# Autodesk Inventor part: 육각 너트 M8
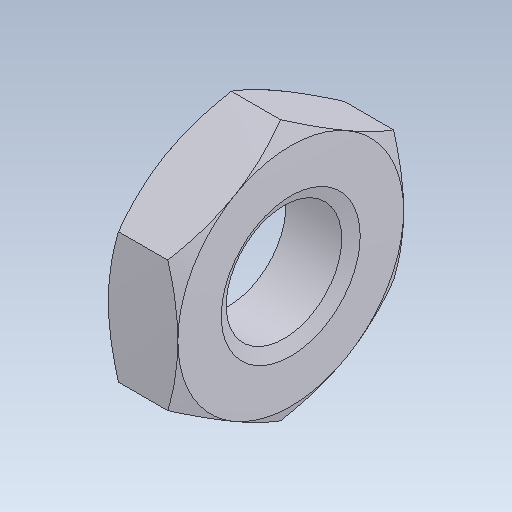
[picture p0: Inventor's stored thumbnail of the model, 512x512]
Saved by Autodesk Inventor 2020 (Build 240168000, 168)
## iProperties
Created: 2024-04
Part Number: 육각 너트 M8
Material: 강철, 연강
Description: 6각 너트 및 6각 가는 너트 - 이중 모따기
Document SubType Name: Modeling
Designer: oem
Density: 7.86 g/cm^3
Appearance: 기본값
Mass: 3.42669 g
Surface Area: 4.61759 cm^2
Volume: 0.435966 cm^3
Sending System: Autodesk Inventor 2025
Preprocessor: ST-DEVELOPER v20
Author: jhkim
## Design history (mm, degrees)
feature "Solid1"
node "솔리드1"
